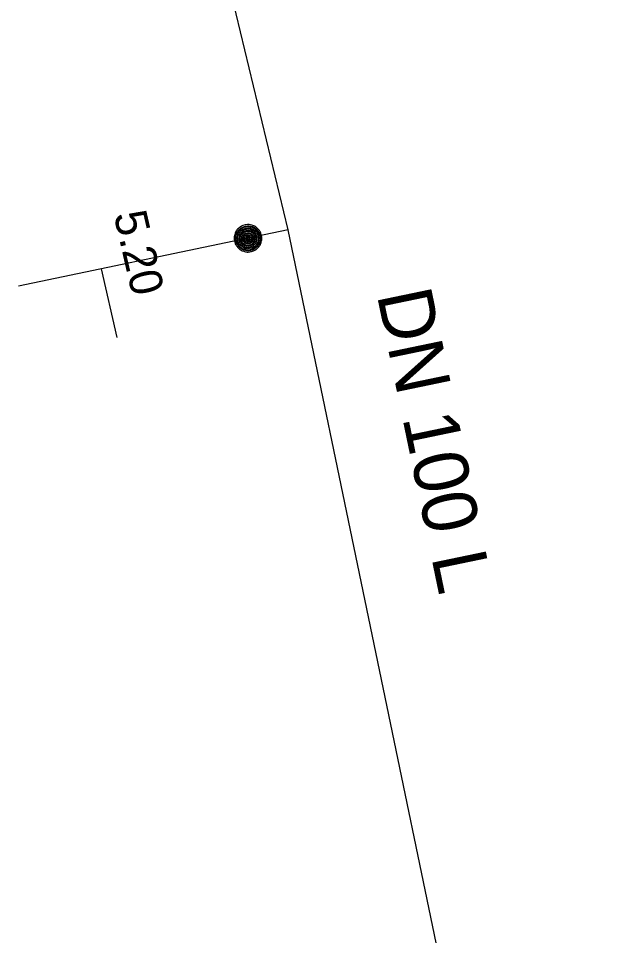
# Model space of a CAD drawing. Extents: x -820257 to -819974, y -1070894 to -1070484.
# Drawn here: x -820214.25 to -820192.29, y -1070551.67 to -1070518.08 of the extents above; entities that cross this region are included whole.
import ezdxf

# ---------------------------------------------------------------- set-up
doc = ezdxf.new("R2010")
doc.units = 0
for name, color, linetype in [('Oměrka vodovodu', 7, 'Continuous'), ('Oměrka-text', 7, 'Continuous'), ('Přípojka vodovodu', 7, 'Continuous'), ('Přípojkový uzávěr', 7, 'Continuous'), ('Roz-řad', 7, 'Continuous'), ('Roz-řad-popis základní', 7, 'Continuous')]:
    doc.layers.add(name, color=color, linetype=linetype)

msp = doc.modelspace()

# ---------------------------------------------------------------- linework, layer by layer
at = {"layer": 'Oměrka vodovodu'}
msp.add_line((-820211.216, -1070527.258), (-820210.636, -1070529.767), dxfattribs=at)
at = {"layer": 'Přípojka vodovodu'}
msp.add_lwpolyline([(-820204.367, -1070525.825), (-820205.835, -1070526.133), (-820214.248, -1070527.893)], dxfattribs=at)
at = {"layer": 'Přípojkový uzávěr'}
for points in [[(-820205.938, -1070525.644), (-820205.815, -1070525.618), (-820205.684, -1070525.657), (-820205.554, -1070525.695), (-820205.463, -1070525.799), (-820205.372, -1070525.903), (-820205.346, -1070526.031), (-820205.319, -1070526.158), (-820205.359, -1070526.288), (-820205.399, -1070526.418), (-820205.502, -1070526.507), (-820205.605, -1070526.596), (-820205.733, -1070526.623), (-820205.86, -1070526.649), (-820205.99, -1070526.609), (-820206.12, -1070526.569), (-820206.209, -1070526.466), (-820206.298, -1070526.363), (-820206.324, -1070526.236), (-820206.351, -1070526.108), (-820206.31, -1070525.976), (-820206.269, -1070525.845), (-820206.165, -1070525.757), (-820206.062, -1070525.67), (-820205.938, -1070525.644)], [(-820205.928, -1070525.69), (-820206.04, -1070525.713), (-820206.134, -1070525.792), (-820206.228, -1070525.872), (-820206.266, -1070525.991), (-820206.303, -1070526.11), (-820206.278, -1070526.226), (-820206.254, -1070526.342), (-820206.174, -1070526.435), (-820206.094, -1070526.528), (-820205.976, -1070526.564), (-820205.857, -1070526.601), (-820205.743, -1070526.577), (-820205.627, -1070526.553), (-820205.533, -1070526.472), (-820205.44, -1070526.391), (-820205.404, -1070526.274), (-820205.367, -1070526.156), (-820205.391, -1070526.041), (-820205.416, -1070525.925), (-820205.498, -1070525.83), (-820205.581, -1070525.736), (-820205.699, -1070525.701), (-820205.816, -1070525.666), (-820205.928, -1070525.69)], [(-820205.921, -1070525.723), (-820205.818, -1070525.702), (-820205.709, -1070525.734), (-820205.6, -1070525.766), (-820205.524, -1070525.853), (-820205.447, -1070525.94), (-820205.425, -1070526.048), (-820205.403, -1070526.154), (-820205.436, -1070526.263), (-820205.469, -1070526.372), (-820205.556, -1070526.446), (-820205.643, -1070526.521), (-820205.75, -1070526.543), (-820205.856, -1070526.566), (-820205.965, -1070526.532), (-820206.074, -1070526.499), (-820206.149, -1070526.412), (-820206.223, -1070526.326), (-820206.245, -1070526.219), (-820206.267, -1070526.112), (-820206.233, -1070526.002), (-820206.199, -1070525.892), (-820206.112, -1070525.818), (-820206.025, -1070525.745), (-820205.921, -1070525.723)], [(-820205.913, -1070525.766), (-820206.066, -1070525.798), (-820206.15, -1070525.928), (-820206.234, -1070526.058), (-820206.202, -1070526.21), (-820206.17, -1070526.362), (-820206.04, -1070526.447), (-820205.91, -1070526.532), (-820205.759, -1070526.5), (-820205.606, -1070526.468), (-820205.521, -1070526.339), (-820205.436, -1070526.209), (-820205.468, -1070526.057), (-820205.5, -1070525.904), (-820205.629, -1070525.819), (-820205.758, -1070525.734), (-820205.913, -1070525.766)], [(-820205.903, -1070525.811), (-820205.769, -1070525.783), (-820205.656, -1070525.858), (-820205.543, -1070525.932), (-820205.515, -1070526.065), (-820205.487, -1070526.199), (-820205.561, -1070526.312), (-820205.636, -1070526.426), (-820205.769, -1070526.454), (-820205.903, -1070526.482), (-820206.016, -1070526.407), (-820206.129, -1070526.333), (-820206.157, -1070526.2), (-820206.185, -1070526.066), (-820206.111, -1070525.953), (-820206.037, -1070525.839), (-820205.903, -1070525.811)], [(-820205.895, -1070525.85), (-820206.013, -1070525.875), (-820206.078, -1070525.975), (-820206.143, -1070526.074), (-820206.119, -1070526.192), (-820206.094, -1070526.309), (-820205.994, -1070526.374), (-820205.895, -1070526.439), (-820205.777, -1070526.415), (-820205.66, -1070526.39), (-820205.595, -1070526.29), (-820205.529, -1070526.19), (-820205.554, -1070526.073), (-820205.578, -1070525.956), (-820205.678, -1070525.891), (-820205.777, -1070525.825), (-820205.895, -1070525.85)], [(-820205.887, -1070525.889), (-820205.784, -1070525.867), (-820205.698, -1070525.924), (-820205.612, -1070525.981), (-820205.59, -1070526.082), (-820205.569, -1070526.184), (-820205.626, -1070526.27), (-820205.682, -1070526.357), (-820205.784, -1070526.378), (-820205.885, -1070526.399), (-820205.972, -1070526.343), (-820206.058, -1070526.286), (-820206.08, -1070526.185), (-820206.101, -1070526.083), (-820206.045, -1070525.997), (-820205.989, -1070525.91), (-820205.887, -1070525.889)], [(-820205.877, -1070525.934), (-820205.96, -1070525.951), (-820206.006, -1070526.022), (-820206.052, -1070526.092), (-820206.034, -1070526.174), (-820206.017, -1070526.257), (-820205.947, -1070526.303), (-820205.877, -1070526.349), (-820205.794, -1070526.332), (-820205.712, -1070526.314), (-820205.666, -1070526.244), (-820205.619, -1070526.174), (-820205.637, -1070526.091), (-820205.654, -1070526.009), (-820205.724, -1070525.963), (-820205.795, -1070525.917), (-820205.877, -1070525.934)], [(-820205.87, -1070525.968), (-820205.801, -1070525.954), (-820205.743, -1070525.991), (-820205.685, -1070526.029), (-820205.671, -1070526.098), (-820205.656, -1070526.167), (-820205.695, -1070526.225), (-820205.733, -1070526.283), (-820205.801, -1070526.298), (-820205.87, -1070526.312), (-820205.928, -1070526.274), (-820205.986, -1070526.236), (-820206, -1070526.167), (-820206.015, -1070526.098), (-820205.977, -1070526.04), (-820205.939, -1070525.982), (-820205.87, -1070525.968)], [(-820205.861, -1070526.011), (-820205.912, -1070526.022), (-820205.94, -1070526.065), (-820205.968, -1070526.108), (-820205.957, -1070526.159), (-820205.947, -1070526.209), (-820205.903, -1070526.238), (-820205.86, -1070526.266), (-820205.81, -1070526.256), (-820205.759, -1070526.245), (-820205.73, -1070526.202), (-820205.702, -1070526.158), (-820205.713, -1070526.108), (-820205.723, -1070526.057), (-820205.766, -1070526.029), (-820205.809, -1070526), (-820205.861, -1070526.011)], [(-820205.852, -1070526.057), (-820205.819, -1070526.05), (-820205.792, -1070526.067), (-820205.766, -1070526.085), (-820205.759, -1070526.117), (-820205.752, -1070526.149), (-820205.77, -1070526.176), (-820205.787, -1070526.203), (-820205.82, -1070526.21), (-820205.851, -1070526.216), (-820205.878, -1070526.199), (-820205.905, -1070526.181), (-820205.912, -1070526.149), (-820205.919, -1070526.117), (-820205.901, -1070526.09), (-820205.883, -1070526.063), (-820205.852, -1070526.057)], [(-820205.845, -1070526.087), (-820205.864, -1070526.091), (-820205.875, -1070526.107), (-820205.885, -1070526.123), (-820205.881, -1070526.143), (-820205.877, -1070526.162), (-820205.861, -1070526.173), (-820205.845, -1070526.183), (-820205.826, -1070526.179), (-820205.806, -1070526.175), (-820205.796, -1070526.159), (-820205.786, -1070526.143), (-820205.79, -1070526.124), (-820205.794, -1070526.104), (-820205.81, -1070526.094), (-820205.826, -1070526.083), (-820205.845, -1070526.087)]]:
    msp.add_open_spline(points, degree=3, dxfattribs=at)
at = {"layer": 'Roz-řad'}
msp.add_lwpolyline([(-820192.294, -1070583.934), (-820204.367, -1070525.825), (-820206.422, -1070517.249), (-820209.898, -1070501.039), (-820209.965, -1070500.833), (-820212.767, -1070486.628), (-820213.283, -1070484.403)], dxfattribs=at)

# ---------------------------------------------------------------- texts
at = {"layer": 'Oměrka-text'}
msp.add_text(' 5.20', height=1.2, rotation=283.0163, dxfattribs=at).set_placement((-820210.861, -1070524.832))
at = {"layer": 'Roz-řad-popis základní'}
msp.add_text('DN 100 L', height=2, rotation=281.737, dxfattribs=at).set_placement((-820201.121, -1070528.191))

doc.saveas('drawing.dxf')
